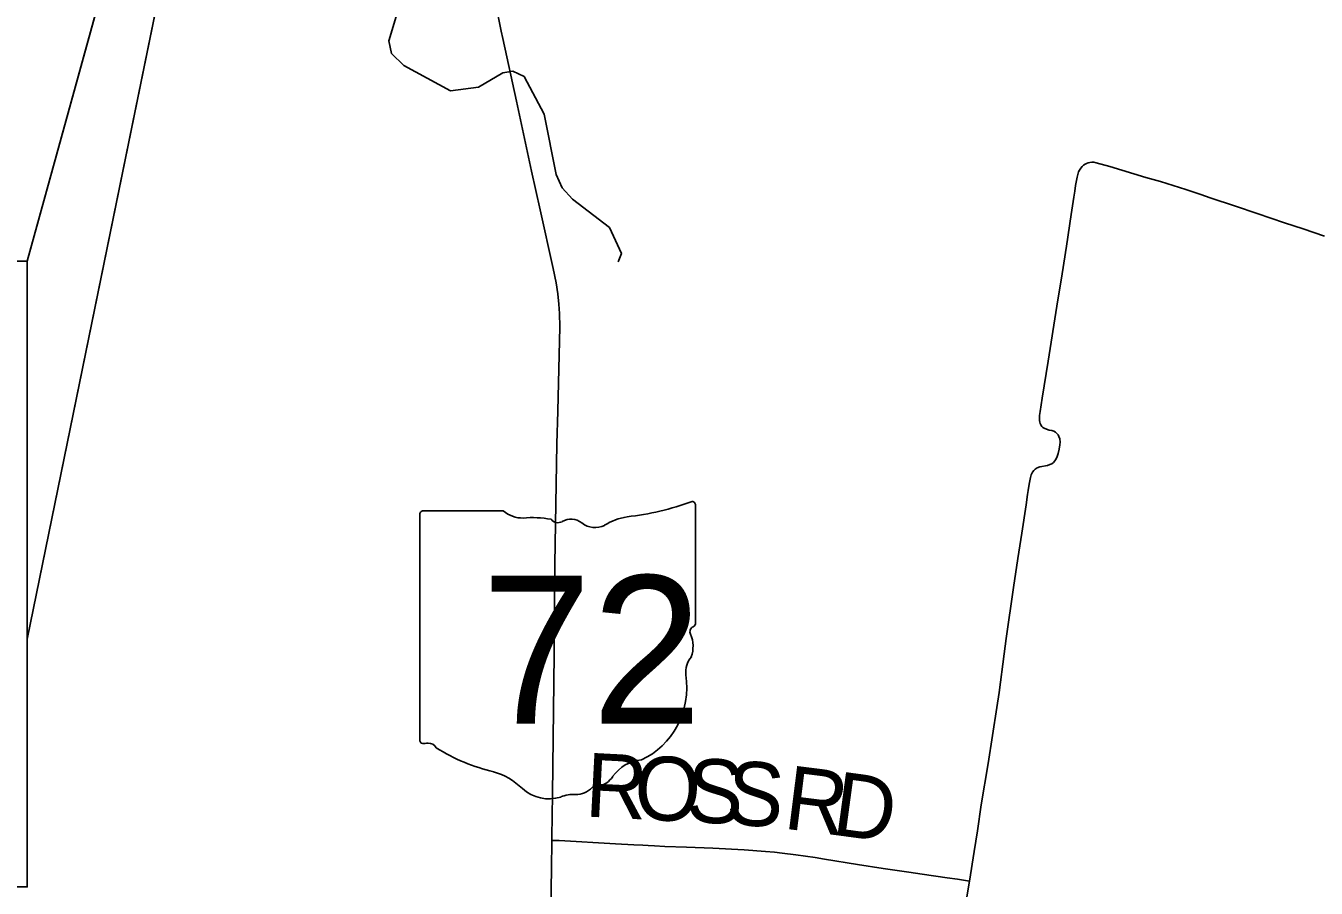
# Model space of a CAD drawing. Extents: x -13.9 to 69.1, y -25.2 to 26.1.
# Drawn here: x 3.981 to 5.08, y 16.445 to 17.179 of the extents above; entities that cross this region are included whole.
import ezdxf

# ---------------------------------------------------------------- set-up
doc = ezdxf.new("R2010")
doc.units = 0
for name, color, linetype in [('GM_X_Minor_River', 7, 'Continuous'), ('GM_X_State_Location', 7, 'Continuous'), ('GM_X_State_Route', 7, 'Continuous'), ('GM_X_State_Shield', 7, 'Continuous'), ('GM_X_Township_Road', 7, 'Continuous'), ('GM_X_Township_Road_Text', 7, 'Continuous'), ('SH_Text', 7, 'Continuous')]:
    doc.layers.add(name, color=color, linetype=linetype)

msp = doc.modelspace()

# ---------------------------------------------------------------- linework, layer by layer
at = {"layer": 'GM_X_Minor_River'}
msp.add_lwpolyline([(4.3378, 17.3552), (4.3317, 17.2792), (4.316, 17.2308), (4.3, 17.1984), (4.2904, 17.1663), (4.2925, 17.1557), (4.3032, 17.1453), (4.3429, 17.1238), (4.3666, 17.127), (4.3873, 17.1393), (4.3958, 17.1406), (4.4055, 17.136), (4.4225, 17.1041), (4.4328, 17.0526), (4.438, 17.0412), (4.4466, 17.0316), (4.4782, 17.0074), (4.4883, 16.9854), (4.4855, 16.9781)], dxfattribs=at)
at = {"layer": 'GM_X_State_Route'}
for points in [[(4.3874, 17.1683), (4.386, 17.1747), (4.3811, 17.1985), (4.3732, 17.2356), (4.368, 17.2587), (4.3611, 17.2899), (4.3569, 17.3084), (4.3505, 17.3379), (4.3428, 17.3727), (4.3371, 17.3975), (4.3348, 17.4055)], [(4.4281, 16.4288), (4.4287, 16.4609), (4.4291, 16.4854), (4.4291, 16.4883), (4.4296, 16.5246), (4.4311, 16.6441), (4.4315, 16.7208), (4.4333, 16.8231), (4.4341, 16.851), (4.4358, 16.923), (4.4356, 16.9343), (4.4351, 16.9421), (4.4341, 16.951), (4.4327, 16.9604), (4.4303, 16.9726), (4.4191, 17.0224), (4.4119, 17.0554), (4.399, 17.115), (4.3874, 17.1683)]]:
    msp.add_lwpolyline(points, dxfattribs=at)
at = {"layer": 'GM_X_State_Shield'}
for p, q in [((4.5513, 16.6707), (4.5513, 16.7709)), ((4.3167, 16.7628), (4.3167, 16.5713)), ((4.3877, 16.7661), (4.3191, 16.7661)), ((4.5513, 16.6707), (4.5513, 16.6707))]:
    msp.add_line(p, q, dxfattribs=at)
for centre, major_axis, start_param, end_param in [((4.4678, 17.0273), (0, 0.2676), 3.243598, 3.471573), ((4.5487, 16.7713), (0, 0.00281), 4.570356, 6.418239), ((4.3194, 16.7632), (0, 0.00292), 0.141897, 1.712693), ((4.4041, 16.7884), (0, 0.0284), 2.471727, 3.160999), ((4.4128, 16.6586), (0, 0.1018), 6.117147, 6.370247), ((4.4343, 16.7642), (0, 0.00818), 2.265299, 3.614618), ((4.4455, 16.7421), (0, 0.017), 5.663012, 6.791794), ((4.4995, 16.7076), (0, 0.0538), 0.128215, 0.537018), ((4.4659, 16.7724), (0, 0.0205), 2.510764, 3.574926), ((4.5507, 16.6633), (0, 0.00435), 0.313182, 2.100276), ((4.525, 16.6506), (0, 0.0261), 4.363898, 5.125152), ((4.5485, 16.6703), (0, 0.00301), 3.483744, 4.847375), ((4.5607, 16.6287), (0, 0.019), 0.816927, 1.691741), ((4.4817, 16.616), (0, 0.0669), 3.530956, 4.869221), ((4.3195, 16.5709), (0, 0.00295), 1.430444, 2.937505), ((4.3199, 16.5905), (0, 0.0225), 3.095149, 3.326665), ((4.3242, 16.5602), (0, 0.00812), 5.231596, 6.340288), ((4.4194, 16.7323), (0, 0.1933), 2.625201, 2.918164), ((4.5079, 16.5175), (0, 0.0367), 0.076849, 0.917637), ((4.3658, 16.4852), (0, 0.0605), 5.535908, 6.035976), ((4.4648, 16.5527), (0, 0.0216), 3.366272, 4.071454), ((4.4266, 16.5593), (0, 0.0384), 2.455685, 3.425939), ((4.4498, 16.5449), (0, 0.0204), 3.120248, 3.936577), ((4.467, 16.5264), (0, 0.00576), 5.859973, 7.027541), ((4.4472, 16.4931), (0, 0.0315), 6.208051, 6.653369)]:
    msp.add_ellipse(centre, major_axis=major_axis, ratio=0.929448, start_param=start_param, end_param=end_param, dxfattribs=at)
at = {"layer": 'GM_X_Township_Road'}
for points in [[(4.7845, 16.4509), (4.7886, 16.476), (4.7913, 16.4936), (4.7946, 16.5159), (4.8003, 16.5511), (4.8079, 16.5986), (4.8097, 16.6115), (4.814, 16.6444), (4.8157, 16.6574), (4.8221, 16.7008), (4.8258, 16.7255), (4.8291, 16.7472), (4.8328, 16.7712), (4.8339, 16.7801), (4.8345, 16.7836), (4.8353, 16.7888), (4.8365, 16.7946), (4.8371, 16.7969), (4.8382, 16.799), (4.8392, 16.8004), (4.8404, 16.8016), (4.8422, 16.8028), (4.8443, 16.8036), (4.8509, 16.8049), (4.8528, 16.8055), (4.8545, 16.8063), (4.8559, 16.8073), (4.8571, 16.8087), (4.8582, 16.8105), (4.8592, 16.8125), (4.86, 16.8151), (4.8608, 16.8188), (4.8615, 16.8223), (4.8616, 16.8246), (4.8614, 16.8274), (4.8607, 16.8294), (4.8599, 16.8309), (4.859, 16.832), (4.8576, 16.8332), (4.8564, 16.8339), (4.8545, 16.8345), (4.8524, 16.835), (4.8487, 16.8362), (4.8471, 16.8371), (4.8461, 16.8381), (4.8452, 16.8394), (4.8447, 16.8404), (4.8443, 16.8416), (4.8441, 16.8432), (4.844, 16.8449), (4.8441, 16.8473), (4.8446, 16.8509), (4.8464, 16.862), (4.8514, 16.8937), (4.859, 16.9406), (4.8635, 16.9681), (4.8672, 16.9915), (4.8712, 17.0185), (4.8733, 17.0332), (4.8741, 17.0385), (4.8748, 17.0432), (4.8755, 17.0474), (4.8761, 17.0502), (4.8767, 17.0527), (4.8774, 17.0548), (4.8783, 17.0564), (4.8792, 17.058), (4.8803, 17.0593), (4.8817, 17.0606), (4.8829, 17.0614), (4.8841, 17.062), (4.8856, 17.0625), (4.8871, 17.0629), (4.8886, 17.0631), (4.8904, 17.063), (4.8924, 17.0626), (4.9039, 17.0593), (4.9347, 17.05), (4.947, 17.0465), (4.9688, 17.0398), (4.9815, 17.0356), (4.9893, 17.0328), (5.011, 17.0255), (5.0294, 17.0193), (5.0526, 17.0115), (5.0684, 17.0062), (5.0868, 17)], [(4.4291, 16.4854), (4.4354, 16.4853), (4.4834, 16.4827), (4.4989, 16.4818), (4.5066, 16.4813), (4.511, 16.4811), (4.5165, 16.4808), (4.5253, 16.4804), (4.5436, 16.4798), (4.5662, 16.4788), (4.5927, 16.4775), (4.6109, 16.4761), (4.6186, 16.4754), (4.6252, 16.4747), (4.6367, 16.4732), (4.6531, 16.4708), (4.6612, 16.4695), (4.6891, 16.4651), (4.711, 16.4616), (4.7329, 16.4583), (4.7443, 16.4567), (4.7656, 16.4536), (4.7743, 16.4524), (4.7845, 16.4509)], [(4.7801, 16.4239), (4.7845, 16.4509)]]:
    msp.add_lwpolyline(points, dxfattribs=at)
at = {"layer": 'SH_Text'}
for p, q in [((3.9826, 16.9789), (4.2351, 17.8933)), ((4.2351, 17.8933), (3.9826, 16.6568))]:
    msp.add_line(p, q, dxfattribs=at)
for points in [[(3.9826, 16.9789), (4.2351, 17.8933), (3.9826, 16.6568)], [(2.0965, 16.9789), (3.9826, 16.9789), (3.9826, 16.4459), (2.0965, 16.4459)]]:
    msp.add_lwpolyline(points, close=True, dxfattribs=at)

# ---------------------------------------------------------------- texts
at = {"layer": 'GM_X_State_Location'}
for s in ['s', 'r']:
    msp.add_text(s, height=0.000181, dxfattribs=at).set_placement((4.4314, 16.6543))
msp.add_text('72', height=0.000181, rotation=0, dxfattribs=at).set_placement((4.389, 16.6411))
at = {"layer": 'GM_X_State_Shield'}
msp.add_text('72', height=0.12619, dxfattribs=at).set_placement((4.3692, 16.5848))
at = {"layer": 'GM_X_Township_Road_Text'}
for s, height, rotation, p in [('R', 0.0544, 357.0513, (4.4566, 16.5059)), ('O', 0.0544, 357.0507, (4.4981, 16.5038)), ('S', 0.0544, 356.9779, (4.5425, 16.5015)), ('S', 0.0544, 355.7292, (4.5763, 16.4997)), ('R', 0.0543, 352.8502, (4.6252, 16.4957)), ('D', 0.0543, 352.2846, (4.6663, 16.4906))]:
    msp.add_text(s, height=height, rotation=rotation, dxfattribs=at).set_placement(p)

doc.saveas('drawing.dxf')
